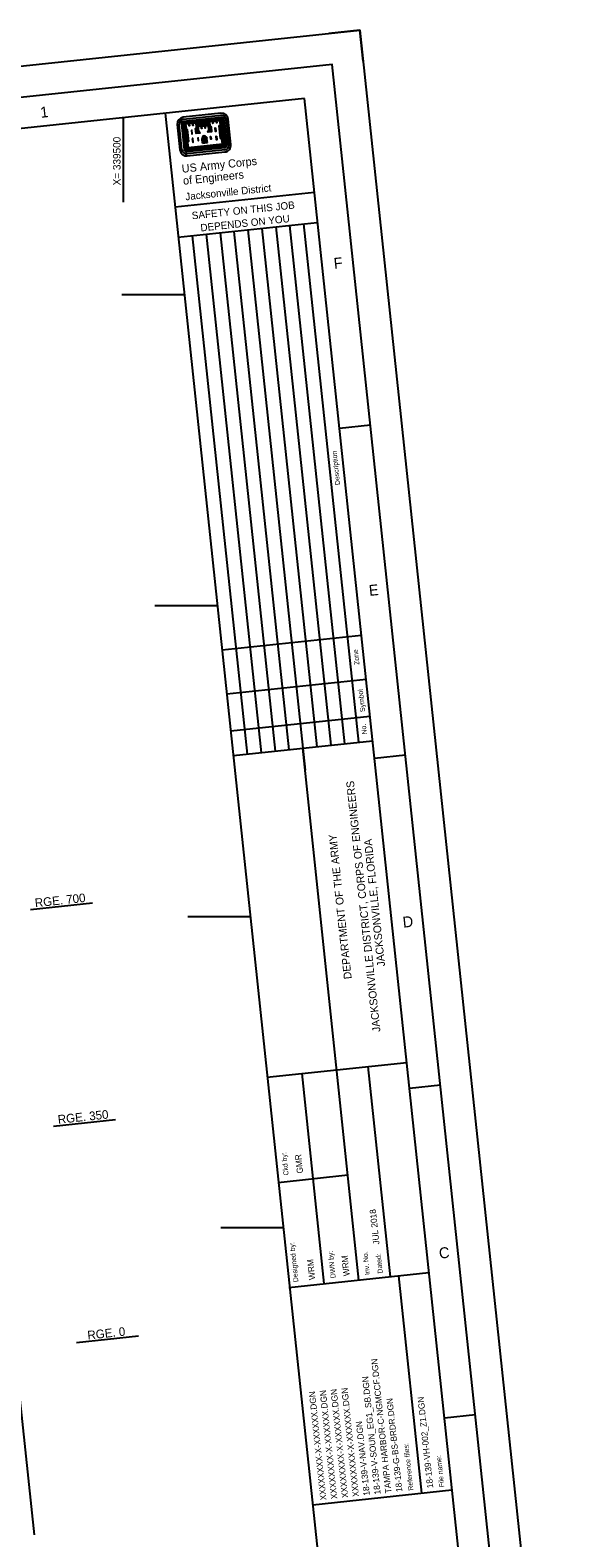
# Model space of a CAD drawing. Extents: x 335504 to 340238, y 1183580 to 1187425.
# Drawn here: x 339350 to 340238, y 1185001 to 1187425 of the extents above; entities that cross this region are included whole.
import ezdxf

# ---------------------------------------------------------------- set-up
doc = ezdxf.new("R2010")
doc.units = 0
for name, color, linetype in [('G-ANNO-NPLT', 7, 'Continuous'), ('G-ANNO-TEXT-DRWG', 7, 'Continuous'), ('G-ANNO-TEXT-LOGO', 7, 'Continuous'), ('G-ANNO-TEXT-PROJ', 7, 'Continuous'), ('G-ANNO-TEXT-TTLB', 7, 'Continuous'), ('G-ANNO-TTLB', 7, 'Continuous'), ('V-ALGN-TEXT', 7, 'Continuous'), ('V-ANNO-MATC', 7, 'Continuous'), ('V-TOPO-COOR-STAT', 7, 'Continuous')]:
    doc.layers.add(name, color=color, linetype=linetype)

msp = doc.modelspace()

# ---------------------------------------------------------------- linework, layer by layer
at = {"layer": 'G-ANNO-NPLT'}
msp.add_lwpolyline([(335504, 1186961.1), (339879.5, 1187424.9), (340237.8, 1184043.9), (335862.4, 1183580.1)], close=True, dxfattribs=at)
msp.add_lwpolyline([(339884.7, 1187375.2), (339879.5, 1187424.9), (339829.7, 1187419.6)], dxfattribs=at)
at = {"layer": 'G-ANNO-TEXT-LOGO'}
for p, q in [((339656.2, 1187291.2), (339595.7, 1187284.8)), ((339596, 1187281.6), (339656.5, 1187288.1)), ((339656.9, 1187284.7), (339596.4, 1187278.3)), ((339657, 1187283.8), (339596.5, 1187277.4)), ((339657, 1187282.9), (339596.6, 1187276.5)), ((339657.1, 1187282.1), (339596.7, 1187275.7)), ((339657.2, 1187281.2), (339596.8, 1187274.8)), ((339617.8, 1187276.2), (339636.3, 1187278.2)), ((339617.9, 1187275.3), (339636.4, 1187277.3)), ((339656.1, 1187280.5), (339660.3, 1187240.9)), ((339656.9, 1187280.6), (339661.2, 1187240.1)), ((339657.8, 1187280.7), (339662.1, 1187239.9)), ((339658.7, 1187280.7), (339663, 1187240)), ((339659.5, 1187280.8), (339663.8, 1187240.1)), ((339660.4, 1187280.9), (339664.7, 1187240.2)), ((339661.3, 1187281), (339665.6, 1187240.3)), ((339664.7, 1187281.4), (339669, 1187240.6)), ((339672.3, 1187241), (339667.9, 1187281.7)), ((339586.2, 1187273.1), (339590.5, 1187232.3)), ((339593.7, 1187232.6), (339589.4, 1187273.4)), ((339592.9, 1187273.8), (339597.2, 1187233)), ((339593.7, 1187273.9), (339598.1, 1187233.1)), ((339594.5, 1187273.9), (339598.9, 1187233.2)), ((339595.4, 1187274), (339599.8, 1187233.3)), ((339596.3, 1187274.1), (339600.7, 1187233.4)), ((339597.2, 1187274.2), (339601.5, 1187233.8)), ((339598, 1187274.3), (339602.2, 1187234.7)), ((339599.6, 1187265.7), (339601.9, 1187244.9)), ((339600.6, 1187264.9), (339602.6, 1187245.9)), ((339618, 1187274.5), (339636.5, 1187276.5)), ((339618.1, 1187273.6), (339636.6, 1187275.6)), ((339618.2, 1187272.7), (339636.7, 1187274.7)), ((339618.3, 1187271.9), (339636.8, 1187273.9)), ((339618.4, 1187271), (339636.9, 1187273)), ((339655.5, 1187270.8), (339657.5, 1187251.8)), ((339656.3, 1187271.6), (339658.5, 1187251)), ((339661.7, 1187239.2), (339601.2, 1187232.8)), ((339661.8, 1187238.4), (339601.3, 1187232)), ((339661.9, 1187237.5), (339601.4, 1187231.1)), ((339661.2, 1187240.1), (339601.5, 1187233.8)), ((339662, 1187236.6), (339601.5, 1187230.2)), ((339662, 1187235.9), (339601.6, 1187229.4)), ((339662.4, 1187232.4), (339601.9, 1187226)), ((339660.3, 1187240.9), (339602.2, 1187234.7)), ((339602.3, 1187222.7), (339662.8, 1187229.1)), ((339626.7, 1187243.3), (339626, 1187249.9)), ((339627.5, 1187243.3), (339626.7, 1187250)), ((339626.7, 1187243.3), (339634.6, 1187244.1)), ((339628.3, 1187243.4), (339627.6, 1187250.1)), ((339629.2, 1187243.5), (339628.5, 1187250.2)), ((339630, 1187243.6), (339629.3, 1187250.3)), ((339631.2, 1187243.7), (339630.5, 1187250.4)), ((339632, 1187243.8), (339631.3, 1187250.5)), ((339632.9, 1187243.9), (339632.2, 1187250.6)), ((339633.8, 1187244), (339633.1, 1187250.7)), ((339634.6, 1187244.1), (339633.9, 1187250.8))]:
    msp.add_line(p, q, dxfattribs=at)
for points in [[(339598.7, 1187274.4), (339599.6, 1187266.5), (339601.4, 1187265), (339603.4, 1187246), (339601.9, 1187244.1), (339602.9, 1187235.4), (339659.5, 1187241.4), (339658.6, 1187250.1), (339656.6, 1187251.7), (339654.6, 1187270.7), (339656.2, 1187272.5), (339655.4, 1187280.4), (339647.9, 1187279.6), (339642.2, 1187279), (339636.8, 1187278.4), (339637.6, 1187270.6), (339639.7, 1187269.1), (339640.4, 1187262.1), (339636.3, 1187261.7), (339636.2, 1187262.4), (339637.8, 1187264.4), (339637, 1187272.1), (339629.5, 1187271.3), (339623.7, 1187270.7), (339618.5, 1187270.2), (339619.3, 1187262.4), (339621.3, 1187260.8), (339621.4, 1187260.1), (339617.2, 1187259.7), (339616.4, 1187266.6), (339618, 1187268.5), (339617.2, 1187276.4), (339609.8, 1187275.6), (339604, 1187275), (339598.7, 1187274.4)], [(339599.6, 1187273.6), (339600.3, 1187267), (339602.3, 1187265.4), (339604.4, 1187245.7), (339602.8, 1187243.7), (339603.6, 1187236.4), (339658.6, 1187242.2), (339657.9, 1187249.6), (339655.8, 1187251.2), (339653.7, 1187270.9), (339655.4, 1187272.9), (339654.7, 1187279.4), (339649.3, 1187278.9), (339649.7, 1187275.8), (339649.2, 1187275.7), (339648.8, 1187278.8), (339643.6, 1187278.2), (339643.9, 1187275.2), (339643.5, 1187275.1), (339643.2, 1187278.2), (339637.8, 1187277.6), (339638.5, 1187271.1), (339640.5, 1187269.5), (339641.3, 1187261.4), (339635.6, 1187260.8), (339635.4, 1187262.7), (339637, 1187264.7), (339636.3, 1187271.2), (339630.9, 1187270.7), (339631.2, 1187267.6), (339630.8, 1187267.5), (339630.5, 1187270.6), (339625.1, 1187270.1), (339625.5, 1187267), (339625, 1187266.9), (339624.6, 1187270), (339619.4, 1187269.4), (339620.1, 1187262.9), (339622, 1187261.3), (339622.2, 1187259.4), (339616.5, 1187258.8), (339615.6, 1187266.8), (339617.2, 1187268.8), (339616.5, 1187275.4), (339611.2, 1187274.8), (339611.6, 1187271.7), (339611.1, 1187271.7), (339610.7, 1187274.8), (339605.4, 1187274.2), (339605.7, 1187271.1), (339605.3, 1187271.1), (339605, 1187274.2), (339599.6, 1187273.6)], [(339608.9, 1187263.8), (339609.5, 1187258), (339610.1, 1187258.1), (339609.5, 1187263.9), (339608.9, 1187263.8)], [(339617.8, 1187266.9), (339617.4, 1187266.3), (339618, 1187260.6), (339619.9, 1187260.8), (339618.4, 1187262), (339617.9, 1187267)], [(339638.3, 1187269), (339638.9, 1187268.6), (339639.5, 1187262.9), (339637.7, 1187262.7), (339638.7, 1187264.2), (339638.2, 1187269.1)], [(339639.9, 1187253.7), (339640.4, 1187249.6), (339639.9, 1187249.6), (339639.4, 1187253.7), (339639.9, 1187253.7)], [(339647.6, 1187267.9), (339648.2, 1187262.1), (339647.7, 1187262.1), (339647.1, 1187267.9), (339647.6, 1187267.9)], [(339649, 1187254.7), (339649.6, 1187248.8), (339649.1, 1187248.8), (339648.5, 1187254.6), (339649, 1187254.7)], [(339610.3, 1187250.6), (339610.9, 1187244.7), (339611.5, 1187244.8), (339610.9, 1187250.6), (339610.3, 1187250.6)], [(339619.4, 1187251.5), (339619.9, 1187247.5), (339620.4, 1187247.5), (339619.9, 1187251.6), (339619.4, 1187251.5)]]:
    msp.add_lwpolyline(points, dxfattribs=at)
for centre, major_axis, start_param, end_param in [((339596.9, 1187274.2), (10.7, 1.1), 1.57078, 3.141576), ((339596.9, 1187274.2), (7.45, 0.79), 1.57078, 3.141576), ((339596.9, 1187274.2), (4, 0.42), 1.57078, 3.141576), ((339596.9, 1187274.2), (3.13, 0.33), 1.57078, 3.141576), ((339657.2, 1187280.6), (10.7, 1.1), 6.283169, 7.853965), ((339657.2, 1187280.6), (7.45, 0.79), 6.28317, 7.853966), ((339657.2, 1187280.6), (4, 0.42), 6.283169, 7.853965), ((339657.2, 1187280.6), (3.13, 0.33), 6.283169, 7.853965), ((339657.2, 1187280.6), (2.27, 0.24), 6.283169, 7.853965), ((339657.2, 1187280.6), (1.41, 0.15), 6.283169, 7.853965), ((339657.2, 1187280.6), (0.543, 0.058), 6.283169, 7.853965), ((339596.9, 1187274.2), (2.27, 0.24), 1.57078, 3.141576), ((339596.9, 1187274.2), (1.41, 0.15), 1.57078, 3.141576), ((339596.9, 1187274.2), (0.543, 0.058), 1.57078, 3.141576), ((339631.4, 1187250.1), (-5.52, -0.59), 4.985832, 6.214359), ((339631.4, 1187250.1), (-4.66, -0.49), 4.947465, 6.21436), ((339631.4, 1187250.1), (-3.8, -0.4), 4.947465, 6.21436), ((339631.4, 1187250.1), (-2.93, -0.31), 4.947465, 6.21436), ((339628.5, 1187249.7), (2.93, 0.31), 0.068794, 1.335689), ((339628.5, 1187249.7), (3.8, 0.4), 0.068795, 1.335689), ((339628.5, 1187249.7), (4.66, 0.49), 0.068795, 1.335689), ((339628.5, 1187249.7), (5.52, 0.59), 0.068795, 1.29842), ((339601.2, 1187233.4), (-10.7, -1.1), 6.28317, 7.853966), ((339601.2, 1187233.4), (-7.45, -0.79), 6.28317, 7.853966), ((339601.2, 1187233.4), (-4, -0.42), 6.28317, 7.853966), ((339601.2, 1187233.4), (-3.13, -0.33), 6.28317, 7.853966), ((339601.2, 1187233.4), (-2.27, -0.24), 6.28317, 7.853966), ((339601.2, 1187233.4), (-1.41, -0.15), 6.28317, 7.853966), ((339601.2, 1187233.4), (-0.543, -0.058), 6.28317, 7.853966), ((339628.5, 1187249.7), (2.07, 0.22), 0.068794, 1.335689), ((339631.4, 1187250.1), (-2.07, -0.22), 4.947465, 6.214359), ((339661.6, 1187239.8), (0.543, 0.058), 4.712373, 6.28317), ((339661.6, 1187239.8), (1.41, 0.15), 4.712373, 6.28317), ((339661.6, 1187239.8), (2.27, 0.24), 4.712373, 6.28317), ((339661.6, 1187239.8), (3.13, 0.33), 4.712373, 6.28317), ((339661.6, 1187239.8), (4, 0.42), 4.712373, 6.28317), ((339661.6, 1187239.8), (-7.45, -0.79), 1.570781, 3.141577), ((339661.6, 1187239.8), (10.7, 1.1), 4.712373, 6.28317)]:
    msp.add_ellipse(centre, major_axis=major_axis, ratio=0.99964, start_param=start_param, end_param=end_param, dxfattribs=at)
at = {"layer": 'G-ANNO-TTLB'}
for p, q in [((339566.8, 1187291.2), (339904.1, 1184109.1)), ((339582.8, 1187140.8), (339806.5, 1187164.5)), ((339587.3, 1187091.9), (339811.1, 1187115.6)), ((339744.4, 1187108.6), (339832.7, 1186275.3)), ((339766.7, 1187110.9), (339855.1, 1186277.7)), ((339789.1, 1187113.3), (339877.4, 1186280.1)), ((339610.1, 1187094.3), (339698.4, 1186261.1)), ((339632.5, 1187096.7), (339720.8, 1186263.4)), ((339654.9, 1187099.1), (339743.2, 1186265.8)), ((339677.2, 1187101.4), (339765.6, 1186268.2)), ((339699.6, 1187103.8), (339787.9, 1186270.6)), ((339722, 1187106.2), (339810.3, 1186272.9)), ((339896.5, 1186789.7), (339846.8, 1186784.4)), ((339658.2, 1186428.8), (339882, 1186452.5)), ((339665.7, 1186358), (339889.5, 1186381.7)), ((339672.1, 1186298.4), (339895.8, 1186322)), ((339676.3, 1186258.7), (339900, 1186282.4)), ((339878.1, 1185415.7), (339788.1, 1186270.6)), ((339788.1, 1186270.6), (339791.8, 1186235.4)), ((339952.7, 1186259.3), (339903, 1186254.1)), ((339730.3, 1185741.6), (339954.8, 1185765.4)), ((339892.2, 1185758.8), (339928, 1185421)), ((339822.4, 1185409.9), (339786.9, 1185747.6)), ((340008.9, 1185729), (339959.2, 1185723.7)), ((339748.2, 1185572.7), (339860.3, 1185584.6)), ((339765.6, 1185403.8), (339990.6, 1185427.7)), ((339941.6, 1185422.5), (339978.6, 1185073)), ((340065.2, 1185198.7), (340015.4, 1185193.4)), ((339803.9, 1185054.5), (340027.6, 1185078.2))]:
    msp.add_line(p, q, dxfattribs=at)
for points in [[(335906.8, 1183635.1), (340182.8, 1184088.3), (339835, 1187369.9), (335559, 1186916.7)], [(339790.6, 1187314.9), (335688.6, 1186880.1), (336025.9, 1183698), (340127.9, 1184132.8)]]:
    msp.add_lwpolyline(points, close=True, dxfattribs=at)
at = {"layer": 'V-ALGN-TEXT'}
for p, q in [((339350.5, 1186011.3), (339450, 1186021.8)), ((339387.4, 1185663.2), (339486.9, 1185673.8)), ((339424.3, 1185315.2), (339523.8, 1185325.7))]:
    msp.add_line(p, q, dxfattribs=at)
at = {"layer": 'V-ANNO-MATC'}
msp.add_line((339356.5, 1185006.3), (339219.5, 1186299.1), dxfattribs=at)
at = {"layer": 'V-TOPO-COOR-STAT'}
for p, q in [((339500, 1187148.4), (339500, 1187284.1)), ((339497.1, 1187000), (339597.6, 1187000)), ((339550.1, 1186500), (339650.6, 1186500)), ((339603.1, 1186000), (339703.6, 1186000)), ((339656.1, 1185500), (339756.6, 1185500))]:
    msp.add_line(p, q, dxfattribs=at)

# ---------------------------------------------------------------- texts
at = {"layer": 'G-ANNO-TEXT-DRWG'}
for s, p in [('GMR', (339788.4, 1185587.4)), ('WRM', (339808, 1185416.4)), ('WRM', (339863.3, 1185422.5)), ('TAMPA HARBOR-C-NGMCCF.DGN', (339930.4, 1185073.3)), ('XXXXXXXX-X-XXXXXX.DGN', (339878.2, 1185067.8)), ('18-139-V-SOUN_EG1_SB.DGN', (339913, 1185071.5)), ('XXXXXXXX-X-XXXXXX.DGN', (339826, 1185062.2)), ('XXXXXXXX-X-XXXXXX.DGN', (339843.4, 1185064.1)), ('XXXXXXXX-X-XXXXXX.DGN', (339860.8, 1185065.9)), ('18-139-VH-002_Z1.DGN', (339997.6, 1185081.5)), ('18-139-V-NAV.DGN', (339895.6, 1185069.6))]:
    msp.add_text(s, height=10, rotation=96.0506, dxfattribs=at).set_placement(p)
at = {"layer": 'G-ANNO-TEXT-PROJ'}
for s, height, p in [('JUL 2018', 10, (339911.1, 1185473.1)), ('18-139-G-BS-BRDR.DGN', 9.8, (339947.9, 1185075.6))]:
    msp.add_text(s, height=height, rotation=96.0506, dxfattribs=at).set_placement(p)
at = {"layer": 'G-ANNO-TEXT-TTLB'}
for s, height, rotation, p in [('US Army Corps', 13.086, 6.0506, (339594, 1187195.6)), ('of Engineers', 13.086, 6.0506, (339596, 1187176.3)), ('Jacksonville District', 11.9, 6.0506, (339599.7, 1187151.2)), ('SAFETY ON THIS JOB', 11.9, 6.0506, (339610.1, 1187120.7)), ('DEPENDS ON YOU', 11.9, 6.0506, (339624, 1187101.2)), ('Description', 8, 96.0506, (339847.9, 1186694)), ('Zone', 8, 96.0506, (339878.9, 1186404.9)), ('Symbol', 8, 96.0506, (339888.1, 1186329.2)), ('No.', 8, 96.0506, (339890.9, 1186293.1)), ('JACKSONVILLE DISTRICT, CORPS OF ENGINEERS', 12.5, 96.0506, (339912.7, 1185815)), ('DEPARTMENT OF THE ARMY', 12.5, 96.0506, (339866.5, 1185900)), ('JACKSONVILLE, FLORIDA', 12.5, 96.0506, (339920.2, 1185920.2)), ('Ckd by:', 8, 96.0506, (339765.1, 1185584.1)), ('Designed by:', 8, 96.0506, (339780.8, 1185412.7)), ('DWN by:', 8, 96.0506, (339840.7, 1185419.1)), ('Inv. No.', 8, 96.0506, (339895.7, 1185424.2)), ('Dated:', 8, 96.0506, (339916.4, 1185426.5)), ('Reference files:', 8, 96.0506, (339965.5, 1185077.5)), ('File name:', 8, 96.0506, (340015.2, 1185083))]:
    msp.add_text(s, height=height, rotation=rotation, dxfattribs=at).set_placement(p)
at = {"layer": 'G-ANNO-TTLB'}
for s, p in [('1', (339366.9, 1187283.9)), ('F', (339838.5, 1187041.1)), ('E', (339895, 1186515.3)), ('D', (339949.3, 1185982)), ('C', (340007.6, 1185449.9))]:
    msp.add_text(s, height=17.5, rotation=6.0506, dxfattribs=at).set_placement(p)
at = {"layer": 'V-ALGN-TEXT'}
for s, p in [('RGE. 700', (339358, 1186014.9)), ('RGE. 350', (339394.9, 1185666.8)), ('RGE. 0', (339442.5, 1185319.9))]:
    msp.add_text(s, height=13.92, rotation=6.0506, dxfattribs=at).set_placement(p)
at = {"layer": 'V-TOPO-COOR-STAT'}
msp.add_text('X= 339500', height=12, rotation=90, dxfattribs=at).set_placement((339495, 1187175.4))

doc.saveas('drawing.dxf')
